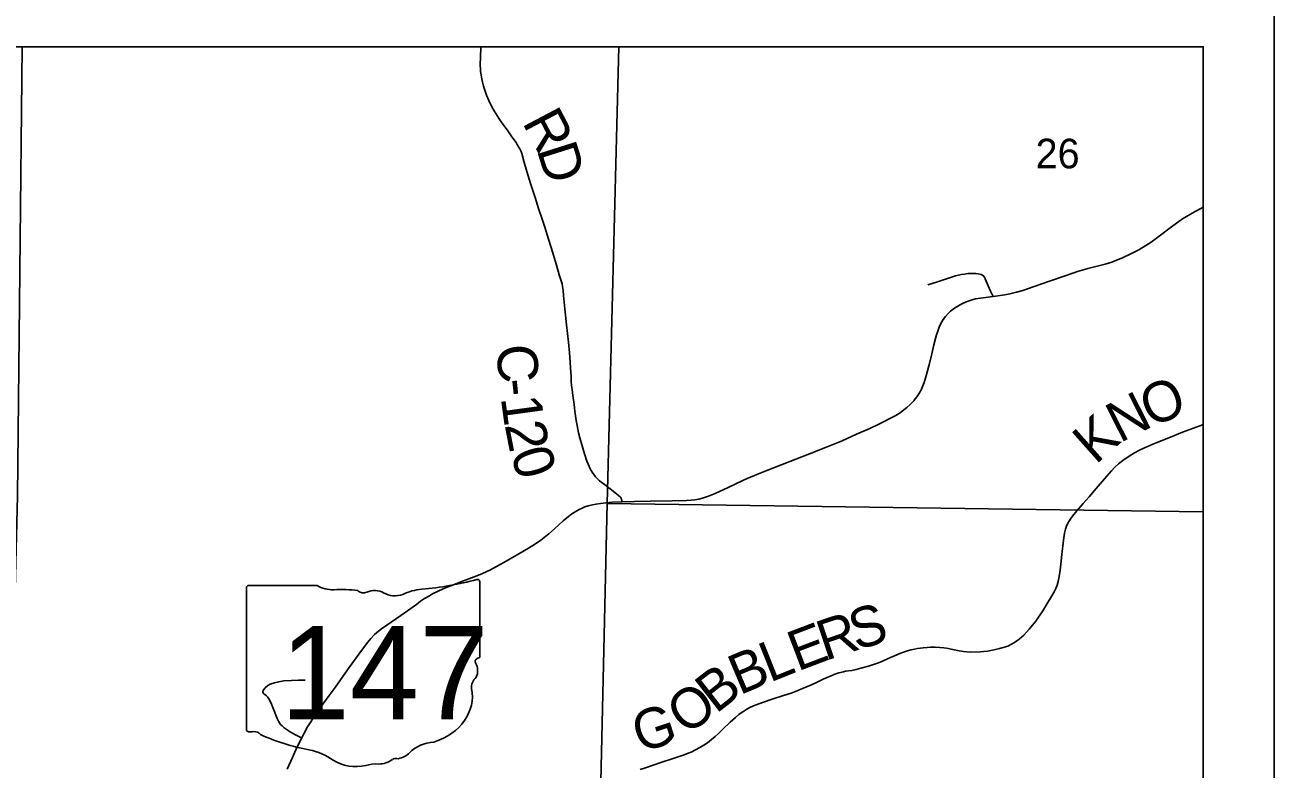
# Model space of a CAD drawing. Extents: x 0 to 34, y 0 to 22.
# Drawn here: x 7.235 to 9, y 19.879 to 20.931 of the extents above; entities that cross this region are included whole.
import ezdxf

# ---------------------------------------------------------------- set-up
doc = ezdxf.new("R2010")
doc.units = 0
for name, color, linetype in [('GM_X_Corporation', 7, 'Continuous'), ('GM_X_County_Road', 7, 'Continuous'), ('GM_X_County_Road_Text', 7, 'Continuous'), ('GM_X_Section_Text', 7, 'Continuous'), ('GM_X_State_Location', 7, 'Continuous'), ('GM_X_State_Route', 7, 'Continuous'), ('GM_X_State_Shield', 7, 'Continuous'), ('GM_X_Township_Road', 7, 'Continuous'), ('GM_X_Township_Road_Text', 7, 'Continuous'), ('GM_X_Township_Text', 7, 'Continuous'), ('SH_Data', 7, 'Continuous')]:
    doc.layers.add(name, color=color, linetype=linetype)

msp = doc.modelspace()

# ---------------------------------------------------------------- linework, layer by layer
at = {"layer": 'GM_X_Corporation'}
for points in [[(7.1227, 14.1), (8.9, 14.1), (8.9, 20.9), (7.231, 20.9), (7.2244, 20.2649), (7.1982, 19.2496), (7.1981, 19.2461), (7.1974, 19.2018), (7.1957, 19.0991), (7.1992, 18.9556), (7.197, 18.9465), (7.1949, 18.8464), (7.1846, 18.5133), (7.1817, 18.3306), (7.1804, 18.2238), (7.1572, 17.4131), (7.1504, 16.6562), (7.1434, 16.3848), (7.1318, 15.4937)], [(8.9, 19.2243), (8.9, 20.9), (7.231, 20.9), (7.2244, 20.2649), (7.1982, 19.2496), (7.2323, 19.2489), (7.3421, 19.2478), (7.6914, 19.2442), (7.7835, 19.2432)], [(8.9, 20.2429), (8.9, 20.9), (8.0743, 20.9), (8.0575, 20.2545)], [(8.9, 19.2258), (8.9, 20.2429), (8.0575, 20.2545), (8.0347, 19.2404)]]:
    msp.add_lwpolyline(points, close=True, dxfattribs=at)
at = {"layer": 'GM_X_County_Road'}
msp.add_lwpolyline([(8.0789, 20.257), (8.078, 20.2603), (8.0772, 20.2619), (8.0763, 20.2635), (8.0736, 20.2659), (8.0636, 20.2739), (8.0518, 20.283), (8.047, 20.2867), (8.0449, 20.2885), (8.0412, 20.2922), (8.0388, 20.2953), (8.0365, 20.2986), (8.0338, 20.3035), (8.031, 20.3091), (8.029, 20.3142), (8.0255, 20.3249), (8.019, 20.3472), (8.0171, 20.3542), (8.016, 20.3594), (8.015, 20.3648), (8.0139, 20.3718), (8.0121, 20.3851), (8.0109, 20.3944), (8.0092, 20.407), (8.0081, 20.4156), (8.0074, 20.4214), (8.0069, 20.4271), (8.0065, 20.4342), (8.0058, 20.4458), (8.0053, 20.4548), (8.0044, 20.4673), (8.0028, 20.4826), (8.0003, 20.5068), (7.9978, 20.5298), (7.996, 20.5485), (7.9954, 20.5554), (7.9945, 20.5612), (7.9938, 20.5648), (7.9929, 20.5678), (7.99, 20.5776), (7.9859, 20.5914), (7.9819, 20.6052), (7.9787, 20.6161), (7.9748, 20.6281), (7.9694, 20.6448), (7.9656, 20.6565), (7.9607, 20.6716), (7.9557, 20.6869), (7.9494, 20.7067), (7.9443, 20.7237), (7.9399, 20.7384), (7.9368, 20.7489), (7.9354, 20.7528), (7.934, 20.7556), (7.9325, 20.7586), (7.9306, 20.7619), (7.9288, 20.7644), (7.923, 20.7726), (7.917, 20.7809), (7.9091, 20.7919), (7.905, 20.7979), (7.8978, 20.8096), (7.8947, 20.8152), (7.8906, 20.8239), (7.8873, 20.8315), (7.8845, 20.8387), (7.8828, 20.8443), (7.8814, 20.8498), (7.8799, 20.8567), (7.8789, 20.8627), (7.8786, 20.8651), (7.8785, 20.8684), (7.8783, 20.8734), (7.8784, 20.887), (7.8789, 20.8971), (7.879, 20.9)], dxfattribs=at)
at = {"layer": 'GM_X_State_Route'}
msp.add_lwpolyline([(7.6054, 19.8791), (7.6127, 19.8956), (7.6191, 19.9096), (7.626, 19.9235), (7.6293, 19.9302), (7.6342, 19.939), (7.6388, 19.9461), (7.6437, 19.9537), (7.6495, 19.9621), (7.6558, 19.9709), (7.6646, 19.9831), (7.673, 19.9947), (7.6839, 20.0102), (7.693, 20.023), (7.7028, 20.0365), (7.7103, 20.0469), (7.7193, 20.0586), (7.7238, 20.064), (7.7288, 20.0693), (7.7343, 20.0741), (7.7388, 20.0776), (7.7461, 20.0825), (7.7661, 20.0961), (7.788, 20.1119), (7.7939, 20.1164), (7.7993, 20.1201), (7.8063, 20.1242), (7.8108, 20.1268), (7.8178, 20.1304), (7.8268, 20.1345), (7.8302, 20.1359), (7.8365, 20.1384), (7.8545, 20.1452), (7.8734, 20.1524), (7.8814, 20.1556), (7.8917, 20.1605), (7.9013, 20.1655), (7.9115, 20.1714), (7.9328, 20.1835), (7.9464, 20.1914), (7.9503, 20.1939), (7.9547, 20.1966), (7.9637, 20.2026), (7.9711, 20.2083), (7.975, 20.2115), (7.9831, 20.2189), (7.9954, 20.2301), (8.003, 20.2362), (8.0078, 20.2398), (8.0123, 20.243), (8.018, 20.2461), (8.0222, 20.2481), (8.0261, 20.2498), (8.0306, 20.2513), (8.0369, 20.2528), (8.042, 20.2538), (8.0483, 20.2547), (8.0556, 20.2556), (8.0647, 20.2564), (8.0789, 20.257), (8.0961, 20.2573), (8.1188, 20.2577), (8.1496, 20.2583), (8.1697, 20.259), (8.1761, 20.2594), (8.1814, 20.2599), (8.187, 20.2607), (8.1925, 20.2619), (8.201, 20.2649), (8.2104, 20.2687), (8.2285, 20.2774), (8.2491, 20.2871), (8.2565, 20.2903), (8.2626, 20.2929), (8.269, 20.2956), (8.2833, 20.3011), (8.3049, 20.3095), (8.3243, 20.3171), (8.3436, 20.3247), (8.3663, 20.3339), (8.3895, 20.3433), (8.4101, 20.3523), (8.4287, 20.3606), (8.4414, 20.3667), (8.4479, 20.3699), (8.458, 20.3751), (8.4655, 20.3791), (8.4715, 20.3829), (8.4768, 20.3867), (8.481, 20.3901), (8.486, 20.3945), (8.491, 20.3998), (8.4931, 20.4023), (8.4955, 20.4056), (8.4982, 20.4097), (8.5004, 20.4133), (8.5018, 20.4162), (8.5039, 20.4209), (8.5058, 20.4257), (8.5072, 20.43), (8.509, 20.4368), (8.5129, 20.4522), (8.5162, 20.4659), (8.5192, 20.4788), (8.5214, 20.4877), (8.5228, 20.493), (8.5247, 20.4982), (8.5268, 20.5037), (8.5288, 20.5081), (8.5307, 20.5113), (8.5326, 20.5147), (8.5359, 20.519), (8.5394, 20.5229), (8.5428, 20.5262), (8.5484, 20.5305), (8.5531, 20.5336), (8.5588, 20.5369), (8.5638, 20.5391), (8.569, 20.5411), (8.5734, 20.5424), (8.5782, 20.5436), (8.5852, 20.5447), (8.6031, 20.5471), (8.6132, 20.5485), (8.6194, 20.5495), (8.6267, 20.551), (8.6363, 20.5532), (8.6451, 20.5557), (8.6612, 20.561), (8.6826, 20.5685), (8.705, 20.5764), (8.7159, 20.5802), (8.7224, 20.5823), (8.7291, 20.5844), (8.7369, 20.5865), (8.7521, 20.5904), (8.7615, 20.5929), (8.7708, 20.5957), (8.7774, 20.5982), (8.7859, 20.6018), (8.7975, 20.6075), (8.809, 20.6132), (8.819, 20.619), (8.8266, 20.624), (8.8358, 20.6307), (8.8571, 20.6471), (8.8655, 20.6531), (8.8708, 20.6567), (8.8763, 20.66), (8.8878, 20.6665), (8.8975, 20.6718), (8.9, 20.6733)], dxfattribs=at)
at = {"layer": 'GM_X_State_Shield'}
for p, q in [((7.8775, 20.0392), (7.8775, 20.1439)), ((7.5479, 20.1355), (7.5479, 19.9354)), ((7.6477, 20.1389), (7.5512, 20.1389)), ((7.8775, 20.0392), (7.8775, 20.0392))]:
    msp.add_line(p, q, dxfattribs=at)
for centre, major_axis, start_param, end_param in [((7.7601, 20.4117), (0.3495, 0), 4.814394, 5.042369), ((7.8739, 20.1443), (0.00367, 0), 6.141152, 7.989035), ((7.5517, 20.1359), (0.00382, 0), 1.712693, 3.28349), ((7.6707, 20.1621), (0.037, 0), 4.042523, 4.731795), ((7.683, 20.0266), (0.133, 0), 1.404758, 1.657858), ((7.7131, 20.1369), (0.0107, 0), 3.836095, 5.185415), ((7.7288, 20.1138), (0.0222, 0), 0.950623, 2.079405), ((7.7575, 20.1455), (0.0267, 0), 4.081561, 5.145723), ((7.8047, 20.0778), (0.0703, 0), 1.699011, 2.107814), ((7.8767, 20.0315), (0.00568, 0), 1.883978, 3.671073), ((7.8736, 20.0388), (0.00393, 0), 5.05454, 6.418171), ((7.8405, 20.0183), (0.0341, 0), 5.934695, 6.695948), ((7.8907, 19.9954), (0.0248, 0), 2.387724, 3.262537), ((7.7797, 19.9821), (0.0874, 0), 5.101752, 6.440018), ((7.5517, 19.9349), (0.00385, 0), 3.00124, 4.508301), ((7.5523, 19.9554), (0.0294, 0), 4.665946, 4.897461), ((7.5583, 19.9238), (0.0106, 0), 0.519207, 1.627899), ((7.6922, 20.1036), (0.2524, 0), 4.195997, 4.488961), ((7.8165, 19.8792), (0.0479, 0), 1.647645, 2.488434), ((7.6169, 19.8454), (0.079, 0), 0.823519, 1.323587), ((7.7591, 19.8884), (0.00752, 0), 1.147584, 2.315152), ((7.7559, 19.916), (0.0282, 0), 4.937069, 5.64225), ((7.7023, 19.9228), (0.0501, 0), 4.026481, 4.996735), ((7.7313, 19.8536), (0.0412, 0), 1.495662, 1.94098), ((7.7349, 19.9078), (0.0267, 0), 4.691044, 5.507374)]:
    msp.add_ellipse(centre, major_axis=major_axis, ratio=0.8, start_param=start_param, end_param=end_param, dxfattribs=at)
at = {"layer": 'GM_X_Township_Road'}
for points in [[(8.5106, 20.5635), (8.5242, 20.5679), (8.5399, 20.5729), (8.5499, 20.576), (8.5542, 20.5772), (8.5579, 20.578), (8.5628, 20.5788), (8.5671, 20.5793), (8.5704, 20.5795), (8.5741, 20.5796), (8.5786, 20.5793), (8.582, 20.5789), (8.5861, 20.578), (8.5882, 20.5771)], [(8.6031, 20.5471), (8.5993, 20.5544), (8.5959, 20.5622), (8.5919, 20.5722), (8.5908, 20.5745), (8.5898, 20.5759), (8.5882, 20.5771)], [(8.1043, 19.8787), (8.1118, 19.8812), (8.1336, 19.8886), (8.151, 19.8944), (8.1662, 19.8995), (8.1721, 19.9016), (8.1765, 19.9034), (8.1826, 19.9064), (8.1885, 19.9096), (8.1942, 19.9131), (8.1993, 19.9166), (8.2052, 19.921), (8.2104, 19.9252), (8.215, 19.9296), (8.2211, 19.9358), (8.2316, 19.9458), (8.2389, 19.952), (8.2438, 19.9562), (8.2483, 19.9596), (8.2516, 19.9618), (8.2549, 19.9639), (8.2594, 19.9664), (8.2642, 19.9687), (8.2684, 19.9703), (8.2773, 19.9735), (8.2923, 19.9784), (8.3069, 19.9832), (8.3176, 19.9868), (8.3239, 19.9891), (8.3303, 19.9917), (8.3439, 19.9973), (8.3514, 20.0008), (8.3628, 20.0062), (8.374, 20.0112), (8.3795, 20.0133), (8.3851, 20.0151), (8.3917, 20.0169), (8.3944, 20.0175), (8.4032, 20.0188), (8.4095, 20.02), (8.4161, 20.0217), (8.4269, 20.0248), (8.4338, 20.027), (8.4412, 20.0296), (8.4468, 20.0319), (8.4537, 20.0349), (8.458, 20.0369), (8.4668, 20.0409), (8.4714, 20.0428), (8.4764, 20.0447), (8.4819, 20.0464), (8.4866, 20.0476), (8.4918, 20.0487), (8.4962, 20.0495), (8.5006, 20.0503), (8.5044, 20.0507), (8.5097, 20.0512), (8.5146, 20.0514), (8.5213, 20.0515), (8.5279, 20.0513), (8.5333, 20.0507), (8.5372, 20.05), (8.5483, 20.0477), (8.555, 20.0465), (8.5613, 20.0456), (8.5659, 20.0451), (8.5717, 20.0447), (8.5848, 20.0449), (8.5893, 20.0453), (8.5953, 20.0461), (8.6044, 20.0478), (8.6121, 20.0495), (8.6171, 20.0509), (8.6236, 20.0532), (8.6288, 20.0557), (8.6321, 20.0575), (8.6345, 20.0589), (8.6398, 20.0627), (8.6464, 20.0683), (8.6502, 20.0726), (8.6542, 20.077), (8.6633, 20.0885), (8.6682, 20.0955), (8.6731, 20.1027), (8.6796, 20.1131), (8.6861, 20.124), (8.6894, 20.1299), (8.6916, 20.1343), (8.6936, 20.1392), (8.6951, 20.1444), (8.6965, 20.1512), (8.6978, 20.1603), (8.6992, 20.1732), (8.7002, 20.1831), (8.7015, 20.1941), (8.7027, 20.2026), (8.7041, 20.2126), (8.7053, 20.2181), (8.7069, 20.2226), (8.7092, 20.2277), (8.7129, 20.2335), (8.7152, 20.2368), (8.7214, 20.244), (8.7305, 20.2546), (8.7386, 20.264), (8.7488, 20.2758), (8.7604, 20.2894), (8.7702, 20.3009), (8.7751, 20.3059), (8.7801, 20.3104), (8.7863, 20.3153), (8.7952, 20.3216), (8.8027, 20.3263), (8.8097, 20.3299), (8.8171, 20.3334), (8.831, 20.3394), (8.8536, 20.3485), (8.8709, 20.3554), (8.8863, 20.3612), (8.8987, 20.3656), (8.9, 20.3661)], [(7.626, 19.9235), (7.6227, 19.925), (7.6164, 19.9281), (7.6098, 19.9318), (7.6038, 19.9356), (7.6011, 19.9375), (7.5982, 19.9402), (7.5961, 19.9424), (7.5944, 19.9447), (7.5932, 19.947), (7.5911, 19.9509), (7.5862, 19.9638), (7.5832, 19.9709), (7.5809, 19.9763), (7.5796, 19.9788), (7.5775, 19.9815), (7.5756, 19.9832), (7.5737, 19.9845), (7.5722, 19.9854), (7.5714, 19.9865), (7.5712, 19.9878), (7.5715, 19.9903), (7.5723, 19.9919), (7.5743, 19.9943), (7.578, 19.9972), (7.5813, 19.9992), (7.5841, 20.0004), (7.5876, 20.0014), (7.5935, 20.0027), (7.6008, 20.0038), (7.6115, 20.0045), (7.6216, 20.0049), (7.6306, 20.005)]]:
    msp.add_lwpolyline(points, dxfattribs=at)
at = {"layer": 'GM_X_Township_Text'}
msp.add_lwpolyline([(7.231, 20.9), (8.9, 20.9), (8.9, 19.2243)], dxfattribs=at)
at = {"layer": 'SH_Data'}
for p, q in [((9, 21), (9, 14)), ((2.1, 20.9), (8.9, 20.9)), ((8.9, 20.9), (8.9, 14.1))]:
    msp.add_line(p, q, dxfattribs=at)

# ---------------------------------------------------------------- texts
at = {"layer": 'GM_X_County_Road_Text'}
for s, rotation, p in [('R', 297.8323, (7.9369, 20.7933)), ('D', 287.5583, (7.9577, 20.7545)), ('C', 274.0272, (7.901, 20.4778)), ('-', 276.2789, (7.9045, 20.4288)), ('1', 277.79, (7.9072, 20.404)), ('2', 281.0908, (7.9126, 20.3658)), ('0', 286.8149, (7.9208, 20.3255))]:
    msp.add_text(s, height=0.0568, rotation=rotation, dxfattribs=at).set_placement(p)
at = {"layer": 'GM_X_Section_Text'}
msp.add_text('26', height=0.04186, rotation=0, dxfattribs=at).set_placement((8.663, 20.7281))
at = {"layer": 'GM_X_State_Location'}
for s in ['s', 'r']:
    msp.add_text(s, height=0.000189, dxfattribs=at).set_placement((7.709, 20.0221))
msp.add_text('147', height=0.000189, rotation=0, dxfattribs=at).set_placement((7.6422, 20.0083))
at = {"layer": 'GM_X_State_Shield'}
msp.add_text('147', height=0.13184, dxfattribs=at).set_placement((7.5958, 19.9495))
at = {"layer": 'GM_X_Township_Road_Text'}
for s, rotation, p in [('O', 22.3223, (8.8255, 20.3616)), ('N', 26.899, (8.782, 20.3395)), ('K', 41.629, (8.7478, 20.3085)), ('S', 17.3756, (8.4098, 20.0466)), ('R', 18.5534, (8.3658, 20.0319)), ('E', 20.7747, (8.3267, 20.017)), ('B', 22.9198, (8.2447, 19.9833)), ('L', 21.7258, (8.2874, 20.0013)), ('B', 37.9456, (8.2113, 19.9566)), ('O', 35.8422, (8.1689, 19.9259)), ('G', 18.1516, (8.1044, 19.9017))]:
    msp.add_text(s, height=0.0568, rotation=rotation, dxfattribs=at).set_placement(p)

doc.saveas('drawing.dxf')
